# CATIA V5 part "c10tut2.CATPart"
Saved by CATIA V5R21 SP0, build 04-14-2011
Part number: tut2
Bounding box of the stored display mesh (mm): x -104.999 to 104.999, y -155 to 550, z -22.499 to 22.486
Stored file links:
  D:\CATIA V5R21 E-RESOURCES\CATIA-V5R21\catia-v5r21-prt\c10-catia-v5r20-prt\c10-catia-v5r21-tut02.CATPart
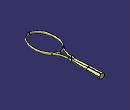
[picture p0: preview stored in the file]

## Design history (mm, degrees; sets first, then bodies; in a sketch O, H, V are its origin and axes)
Body1 (main body)
  Sketch1 on xy-plane, origin (0, 0, 0), H (1, 0, 0), V (0, 1, 0)
    ellipse A1 centre (0, 0) semi-axes 150, 100 rotation 90
    point P1 (100, 0)
    "Radius" A1 = 150
    "Radius" A1 = 100
    coincidence: P1 H, A1 P1
    vertical: A1 V
  Sketch2 on zx-plane, origin (0, 0, 0), H (-1, 0, 0), V (0, 0, 1)
    point P1 (100, 0)
    ellipse A1 centre (100, 0) semi-axes 10, 5 rotation 90
    point P2 (105, 0)
    reference projected line E1 (-100, 0) -> (100, 0) from Sketch1.A1
    "Radius" A1 = 10
    "Radius" A1 = 5
    distance V P1 = 100
    coincidence: P2 H, A1 P2, P1 E1
    vertical: A1 V
  Sweep1: type Unspec, Profile Sketch2, Guide Sketch1
  Sketch3 on xy-plane, origin (0, 0, 0), H (1, 0, 0), V (0, 1, 0)
    line L1 (15, 275) -> (15, 245)
    point P1 (15, 275)
    arc A1 centre (215, 245) radius 200 from (15, 245) to (55, 125) ccw
    point P4 (55, 125)
    radius A1 = 200
    distance L1 V = 15
    distance H P1 = 275
    distance H P4 = 125
    distance P4 V = 55
    vertical: L1 V
    tangency: A1 L1
  Plane1: type Normal, Curve Sketch3, RefPoint Sketch3.P1
  Sketch4 on Plane1, origin (0, 275, 0), H (1, 0, 0), V (0, 0, 1)
    point P1 (15, 0)
    ellipse A1 centre (15, 0) semi-axes 8.75, 4.5 rotation 90
    reference projected point E1 (15, 0) from Sketch3.P1
    "Radius" A1 = 8.75
    "Radius" A1 = 4.5
    vertical: A1 V
    coincidence: P1 E1
  Sweep2: type Unspec, Profile Sketch4, Guide Sketch3
  Symmetry1: ToTransfor Sweep2, Reference yz-plane
  Sketch5 on Plane1, origin (0, 275, 0), H (1, 0, 0), V (0, 0, 1)
    projected curve E1 from Sketch4.A1
    projected curve E2 from Sketch4.A1
    projected curve E3 from edge of Symmetry1
    projected curve E4 from edge of Symmetry1
    line L1 (11.75, 6.052) -> (-11.75, 6.052)
    point P1 (11.75, 6.052)
    point P2 (-11.75, 6.052)
    point P3 (-11.75, -6.052)
    point P4 (11.75, -6.052)
    line L2 (11.75, -6.052) -> (-11.75, -6.052)
    point P5 (-11.75, -6.052)
    length L1 = 23.5
    horizontal: L1 H
    coincidence: P1 E1, P2 E3, L2 P5
    symmetry: P2 P3 H, P1 P4 H, L1 L2 H
  Plane2: type Offset, RefPlane zx-plane, Offset 425
  Sketch6 on Plane2, origin (0, 425, 0), H (-1, 0, 0), V (0, 0, 1)
    ellipse A1 centre (0, 0) semi-axes 22.5, 20 rotation 0
    point P1 (22.5, 0)
    point P2 (0, 20)
    point P3 (-11.75, 17.0562)
    point P4 (11.75, 17.0562)
    point P5 (11.75, -17.0562)
    point P6 (-11.75, -17.0562)
    "Radius" A1 = 22.5
    "Radius" A1 = 20
    distance V P3 = 11.75
    distance P3 P4 = 23.5
    distance P6 P5 H = 23.5
    distance P6 V = 11.75
    coincidence: P1 H, P2 V, A1 P1, A1 P2, P3 A1, P4 A1, P6 A1, A1 P5
    horizontal: A1 H
  Loft1: Sections (Sketch5; Sketch6.A1), SectionCouplingPoints ({coupling CouplingPoints (vertex [element of Sketch5 | element of Sketch5]; Sketch6.P4)}; {coupling CouplingPoints (vertex [element of Sketch5 | element of Sketch5]; Sketch6.P5)}; {coupling CouplingPoints (vertex [element of Sketch5 | element of Sketch5]; Sketch6.P6)}; {coupling CouplingPoints (vertex [element of Sketch5 | element of Sketch5]; Sketch6.P3)})
  Plane3: type Offset, RefPlane zx-plane, Offset 550
  Sketch7 on Plane3, origin (0, 550, 0), H (-1, 0, 0), V (0, 0, 1)
    circle A1 centre (0, 0) radius 22.5
    radius A1 = 22.5
  Blend1: StartLimit {blendlimit Curve edge of Loft1, Point {extremum Reference edge of Loft1, Direction (1, 2, 3)}}, EndLimit {blendlimit Curve Sketch7, Point {extremum Reference Sketch7, Direction (1, 2, 3)}}
  Fill1: Boundary edge of Blend1
  Fill2: Boundary Sketch5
